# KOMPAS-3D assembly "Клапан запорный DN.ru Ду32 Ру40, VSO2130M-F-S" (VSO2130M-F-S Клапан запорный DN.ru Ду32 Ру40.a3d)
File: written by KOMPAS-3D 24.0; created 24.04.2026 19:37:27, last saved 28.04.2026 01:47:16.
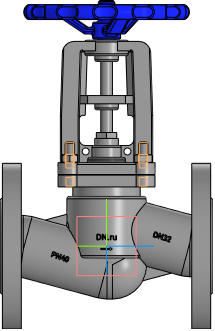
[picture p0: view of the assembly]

Document properties: Автор: DN.ru; Полное имя файла: C:\Работа\ГОТОВЫЕ ИСХОДНИКИ\VSO2130M-F-S Клапан запорный сильфонный DN.ru Ду15-100 Ру40\исходные материалы\DN32\VSO2130M-F-S Клапан запорный DN.ru Ду32 Ру40.a3d

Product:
- Component [detail]: Корпус  | qty 1  | pos. 1  | Масса: 6.9; Автор: R2D2; source file: Korpus.m3d
- Component [detail]: Деталь  | qty 1  | pos. 2  | Масса: 1.659783; Автор: mrdid; source file: rama.m3d
- Component [detail]: Деталь2  | qty 1  | pos. 3  | Масса: 0.594157; Автор: R2D2; additional columns: Типовые; source file: shturval.m3d
- Component [standard]: Шпилька М8-6gx30 ГОСТ 22032-76  | qty 4  | Масса: 0.01271; Раздел спецификации: Стандартные изделия; Рассекать на разрезах: no
- Component [standard]: Гайка М8-6H ГОСТ 5915-70  | qty 4  | Масса: 0.005548; Раздел спецификации: Стандартные изделия; Рассекать на разрезах: no
- Part/product: Клапан запорный DN.ru Ду32 Ру40  | designation VSO2130M-F-S
    Масса: 8
    Раздел спецификации: Прочие изделия
    Примечание: D090-01973

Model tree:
1. Контекстная связь:1  (with: Эскиз:2, Ребро.Элемент выдавливания:14, Контекстная связь (Деталь):1)
2. Контекстная связь:2  (with: Контекстная связь (Деталь):2)
3. Массив по концентрической сетке:1  (with: Грань.Элемент выдавливания:1, Грань.Элемент выдавливания:15, Грань.Элемент выдавливания:3, Грань.Элемент выдавливания:2, Грань.Элемент выдавливания:16, Грань.Элемент выдавливания:17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)  (labels: Грань.Твердое тело1)  (4 pattern instances)
     Шаг 2 = 360; Угол = 8

Referenced files in C:\Работа\ГОТОВЫЕ ИСХОДНИКИ\VSO2130M-F-S Клапан запорный сильфонный DN.ru Ду15-100 Ру40\исходные материалы\DN32\: Korpus.m3d, rama.m3d, shturval.m3d
Referenced files in C:\Program Files\ASCON\KOMPAS-3D v24\Libs\PolynomLib\DATA\vault\Methods\Kompas\3D\: PLib_Stud_1_900.m3d, PLib_Nut_OST92_900.m3d
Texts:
  BOSimple***PART:059b53d5-85de-be37-d9a2-ab7837626634***SHORTLOC:Root±30±20±10±120±10±20[Нет;Без покрытия;Без указания материала;-;8;30;1,25;1,25]
  Крепежное изделие ГОСТ
  BOSimple***PART:bd0d297a-feeb-be2b-2a2a-05cd1c87d412***SHORTLOC:Root±30±10±20±©{}110±10±50±60[Нет;Без покрытия;Без указания материала;-;8;1,25;13]
  Программные изделия  и базы данных
  VSO2130M-F-S
  Деталь2 Деталь2
  Шпилька М8-6gx30 ГОСТ 22032-76 (1)
  cut1
  Гайка М8-6H ГОСТ 5915-70 (1)
  bcut1
  hole1
  hcut1
  hole2
  Плоскость XY.Начало координат
  Plane. Начало координат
